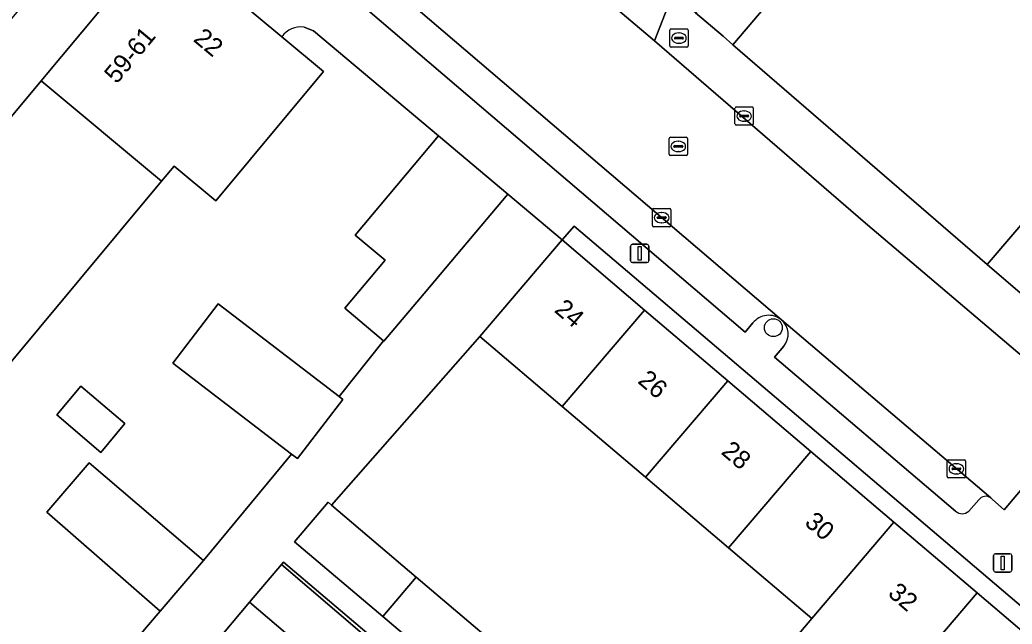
# Model space of a CAD drawing. Extents: x 162523 to 163266, y 381230 to 382050.
# Drawn here: x 162984.5 to 163038.7, y 381611.9 to 381644.9 of the extents above; entities that cross this region are included whole.
import ezdxf

# ---------------------------------------------------------------- set-up
doc = ezdxf.new("R2010")
doc.units = 0
for name, color, linetype in [('IMGEO_Boom', 7, 'Continuous'), ('IMGEO_Brandkraan', 7, 'Continuous'), ('IMGEO_Erf', 7, 'Continuous'), ('IMGEO_Kolk', 7, 'Continuous'), ('IMGEO_Lichtmast', 7, 'Continuous'), ('IMGEO_Muur', 7, 'Continuous'), ('IMGEO_Pand', 7, 'Continuous'), ('IMGEO_Pand_nummerreeks', 7, 'Continuous'), ('IMGEO_Parkeervlak_open', 7, 'Continuous'), ('IMGEO_Rijbaan_lokaal_open', 7, 'Continuous'), ('IMGEO_Rioolput', 7, 'Continuous'), ('IMGEO_Voetpad_open', 7, 'Continuous')]:
    doc.layers.add(name, color=color, linetype=linetype)

msp = doc.modelspace()

# ---------------------------------------------------------------- linework, layer by layer
at = {"layer": 'IMGEO_Boom'}
msp.add_circle((163025.628, 381628.108), 0.489, dxfattribs=at)
at = {"layer": 'IMGEO_Brandkraan'}
for p, q in [((163019.972, 381643.501), (163019.972, 381644.353)), ((163020.047, 381644.427), (163020.899, 381644.427)), ((163020.274, 381643.97), (163020.672, 381643.97)), ((163020.46, 381644.207), (163020.485, 381644.207)), ((163020.973, 381644.353), (163020.973, 381643.501)), ((163020.899, 381643.427), (163020.047, 381643.427)), ((163020.231, 381643.921), (163020.231, 381643.933)), ((163020.669, 381643.884), (163020.271, 381643.884)), ((163020.483, 381643.647), (163020.458, 381643.647)), ((163020.715, 381643.933), (163020.715, 381643.921))]:
    msp.add_line(p, q, dxfattribs=at)
for points in [[(163019.972, 381643.501), (163019.972, 381644.353)], [(163020.047, 381644.427), (163020.899, 381644.427)], [(163020.973, 381644.353), (163020.973, 381643.501)], [(163020.899, 381643.427), (163020.047, 381643.427)]]:
    msp.add_lwpolyline(points, dxfattribs=at)
for centre, radius, start, end in [((163020.049, 381644.351), 0.0765, 91.552, 178.448), ((163020.049, 381644.351), 0.0765, 91.552, 178.448), ((163020.271, 381643.93), 0.0403, 85.8775, 175.7526), ((163020.676, 381643.932), 0.0386, 1.7309, 96.639), ((163020.897, 381644.351), 0.0765, 1.552, 88.448), ((163020.897, 381644.351), 0.0765, 1.552, 88.448), ((163020.049, 381643.503), 0.0765, 181.552, 268.448), ((163020.049, 381643.503), 0.0765, 181.552, 268.448), ((163020.268, 381643.92), 0.0366, 178.938, 274.7102), ((163020.672, 381643.927), 0.043, 264.8664, 352.4533), ((163020.897, 381643.503), 0.0765, 271.552, 358.448), ((163020.897, 381643.503), 0.0765, 271.552, 358.448)]:
    msp.add_arc(centre, radius, start, end, dxfattribs=at)
for centre, major_axis, ratio, start_param, end_param in [((163020.459, 381643.927), (-0.387, 0.002), 0.722429, 4.712389, 7.853982), ((163020.484, 381643.927), (-0.39, 0.002), 0.717154, 1.570796, 4.712389)]:
    msp.add_ellipse(centre, major_axis=major_axis, ratio=ratio, start_param=start_param, end_param=end_param, dxfattribs=at)
at = {"layer": 'IMGEO_Erf'}
for points in [[(163052.984, 381649.884), (163038.896, 381661.976), (163039.043, 381662.152), (163036.865, 381663.973), (163032.907, 381659.241), (163029.084, 381654.669), (163026.979, 381652.153), (163027.1, 381652.052), (163028.379, 381653.56), (163030.41, 381651.829), (163029.157, 381650.331), (163027.372, 381648.229), (163023.415, 381643.568), (163037.297, 381631.564), (163041.391, 381636.346), (163039.229, 381638.189), (163042.925, 381642.504), (163045.087, 381640.661), (163045.268, 381640.873), (163049.144, 381645.4)], [(162990.207, 381622.865), (162988.9, 381621.297), (162986.503, 381623.352), (162987.81, 381624.92)]]:
    msp.add_lwpolyline(points, close=True, dxfattribs=at)
for points in [[(162992.84, 381626.178), (162995.319, 381629.408), (163001.912, 381624.349), (163004.342, 381627.383), (163002.22, 381629.169), (163004.423, 381631.788), (163002.787, 381633.164), (163007.344, 381638.581), (163000.523, 381644.317), (163000, 381644.529)], [(162998.792, 381643.994), (163001.064, 381642.099), (162997.07, 381637.309), (162995.177, 381635.039), (162992.905, 381636.933), (162992.217, 381636.108), (162978.832, 381620.055), (162971.989, 381611.847), (162983.414, 381602.297), (162985.204, 381604.439), (162980.992, 381607.96), (162983.166, 381610.561), (162987.378, 381607.04), (162992.138, 381612.621), (162985.957, 381618.029), (162988.275, 381620.732), (162994.51, 381615.388), (162999.317, 381621.207), (162992.84, 381626.178)], [(163025.811, 381609.964), (163027.724, 381612.212), (163023.184, 381616.074), (163018.644, 381619.935), (163014.104, 381623.797), (163009.603, 381627.625), (163001.502, 381618.411), (163006.131, 381614.483), (163010.681, 381610.623)], [(163003.429, 381611.437), (162998.887, 381615.303), (162998.764, 381615.162), (163003.308, 381611.294)], [(163001.568, 381609.238), (162997.018, 381613.111), (162989.08, 381603.646)]]:
    msp.add_lwpolyline(points, dxfattribs=at)
msp.add_arc((162999.815, 381643.316), 1.227, 81.3199, 146.4554, dxfattribs=at)
at = {"layer": 'IMGEO_Kolk'}
for p, q in [((163023.608, 381640.167), (163024.46, 381640.167)), ((163023.533, 381639.241), (163023.533, 381640.093)), ((163023.792, 381639.661), (163023.792, 381639.673)), ((163024.23, 381639.624), (163023.832, 381639.624)), ((163023.835, 381639.71), (163024.233, 381639.71)), ((163024.021, 381639.947), (163024.046, 381639.947)), ((163024.276, 381639.673), (163024.276, 381639.661)), ((163024.534, 381640.093), (163024.534, 381639.241)), ((163024.46, 381639.167), (163023.608, 381639.167)), ((163024.044, 381639.387), (163024.019, 381639.387)), ((163019.028, 381633.693), (163019.028, 381634.545)), ((163019.103, 381634.619), (163019.955, 381634.619)), ((163019.516, 381634.399), (163019.541, 381634.399)), ((163020.029, 381634.545), (163020.029, 381633.693)), ((163019.287, 381634.113), (163019.287, 381634.125)), ((163019.725, 381634.076), (163019.327, 381634.076)), ((163019.33, 381634.162), (163019.728, 381634.162)), ((163019.539, 381633.839), (163019.514, 381633.839)), ((163019.771, 381634.125), (163019.771, 381634.113)), ((163019.955, 381633.619), (163019.103, 381633.619)), ((163035.12, 381619.971), (163035.12, 381620.823)), ((163035.195, 381620.897), (163036.047, 381620.897)), ((163035.608, 381620.677), (163035.633, 381620.677)), ((163036.121, 381620.823), (163036.121, 381619.971)), ((163035.379, 381620.391), (163035.379, 381620.403)), ((163035.817, 381620.354), (163035.419, 381620.354)), ((163035.422, 381620.44), (163035.82, 381620.44)), ((163035.631, 381620.117), (163035.606, 381620.117)), ((163035.863, 381620.403), (163035.863, 381620.391)), ((163036.047, 381619.897), (163035.195, 381619.897))]:
    msp.add_line(p, q, dxfattribs=at)
for points in [[(163023.608, 381640.167), (163024.46, 381640.167)], [(163023.533, 381639.241), (163023.533, 381640.093)], [(163024.534, 381640.093), (163024.534, 381639.241)], [(163024.46, 381639.167), (163023.608, 381639.167)], [(163019.028, 381633.693), (163019.028, 381634.545)], [(163019.103, 381634.619), (163019.955, 381634.619)], [(163020.029, 381634.545), (163020.029, 381633.693)], [(163019.955, 381633.619), (163019.103, 381633.619)], [(163035.12, 381619.971), (163035.12, 381620.823)], [(163035.195, 381620.897), (163036.047, 381620.897)], [(163036.121, 381620.823), (163036.121, 381619.971)], [(163036.047, 381619.897), (163035.195, 381619.897)]]:
    msp.add_lwpolyline(points, dxfattribs=at)
for centre, radius, start, end in [((163023.61, 381640.091), 0.0765, 91.552, 178.448), ((163023.61, 381640.091), 0.0765, 91.552, 178.448), ((163024.458, 381640.091), 0.0765, 1.552, 88.448), ((163024.458, 381640.091), 0.0765, 1.552, 88.448), ((163023.832, 381639.67), 0.0403, 85.8775, 175.7526), ((163023.829, 381639.66), 0.0366, 178.938, 274.7102), ((163024.233, 381639.667), 0.043, 264.8664, 352.4533), ((163024.237, 381639.672), 0.0386, 1.7309, 96.639), ((163023.61, 381639.243), 0.0765, 181.552, 268.448), ((163023.61, 381639.243), 0.0765, 181.552, 268.448), ((163024.458, 381639.243), 0.0765, 271.552, 358.448), ((163024.458, 381639.243), 0.0765, 271.552, 358.448), ((163019.105, 381634.543), 0.0765, 91.552, 178.448), ((163019.105, 381634.543), 0.0765, 91.552, 178.448), ((163019.953, 381634.543), 0.0765, 1.552, 88.448), ((163019.953, 381634.543), 0.0765, 1.552, 88.448), ((163019.105, 381633.695), 0.0765, 181.552, 268.448), ((163019.105, 381633.695), 0.0765, 181.552, 268.448), ((163019.327, 381634.122), 0.0403, 85.8775, 175.7526), ((163019.324, 381634.112), 0.0366, 178.938, 274.7102), ((163019.728, 381634.119), 0.043, 264.8664, 352.4533), ((163019.732, 381634.124), 0.0386, 1.7309, 96.639), ((163019.953, 381633.695), 0.0765, 271.552, 358.448), ((163019.953, 381633.695), 0.0765, 271.552, 358.448), ((163035.197, 381620.821), 0.0765, 91.552, 178.448), ((163035.197, 381620.821), 0.0765, 91.552, 178.448), ((163036.045, 381620.821), 0.0765, 1.552, 88.448), ((163036.045, 381620.821), 0.0765, 1.552, 88.448), ((163035.419, 381620.4), 0.0403, 85.8775, 175.7526), ((163035.416, 381620.39), 0.0366, 178.938, 274.7102), ((163035.82, 381620.397), 0.043, 264.8664, 352.4533), ((163035.824, 381620.402), 0.0386, 1.7309, 96.639), ((163035.197, 381619.973), 0.0765, 181.552, 268.448), ((163035.197, 381619.973), 0.0765, 181.552, 268.448), ((163036.045, 381619.973), 0.0765, 271.552, 358.448), ((163036.045, 381619.973), 0.0765, 271.552, 358.448)]:
    msp.add_arc(centre, radius, start, end, dxfattribs=at)
for centre, major_axis, ratio, start_param, end_param in [((163024.02, 381639.667), (-0.387, 0.002), 0.722429, 4.712389, 7.853982), ((163024.045, 381639.667), (-0.39, 0.002), 0.717154, 1.570796, 4.712389), ((163019.515, 381634.119), (-0.387, 0.002), 0.722429, 4.712389, 7.853982), ((163019.54, 381634.119), (-0.39, 0.002), 0.717154, 1.570796, 4.712389), ((163035.607, 381620.397), (-0.387, 0.002), 0.722429, 4.712389, 7.853982), ((163035.632, 381620.397), (-0.39, 0.002), 0.717154, 1.570796, 4.712389)]:
    msp.add_ellipse(centre, major_axis=major_axis, ratio=ratio, start_param=start_param, end_param=end_param, dxfattribs=at)
at = {"layer": 'IMGEO_Lichtmast'}
for p, q in [((163017.933, 381632.665), (163018.723, 381632.665)), ((163018.723, 381632.665), (163017.933, 381632.665)), ((163017.833, 381631.765), (163017.833, 381632.565)), ((163017.833, 381632.565), (163017.833, 381631.765)), ((163018.823, 381632.565), (163018.823, 381631.765)), ((163018.823, 381631.765), (163018.823, 381632.565)), ((163018.723, 381631.665), (163017.933, 381631.665)), ((163017.933, 381631.665), (163018.723, 381631.665)), ((163037.655, 381614.857), (163037.655, 381615.657)), ((163037.655, 381615.657), (163037.655, 381614.857)), ((163037.755, 381615.757), (163038.545, 381615.757)), ((163038.545, 381615.757), (163037.755, 381615.757)), ((163038.645, 381615.657), (163038.645, 381614.857)), ((163038.645, 381614.857), (163038.645, 381615.657)), ((163038.545, 381614.757), (163037.755, 381614.757)), ((163037.755, 381614.757), (163038.545, 381614.757))]:
    msp.add_line(p, q, dxfattribs=at)
for points in [[(163018.253, 381632.54), (163018.403, 381632.54), (163018.403, 381631.79), (163018.253, 381631.79), (163018.253, 381632.54)], [(163038.075, 381615.632), (163038.225, 381615.632), (163038.225, 381614.882), (163038.075, 381614.882), (163038.075, 381615.632)]]:
    msp.add_lwpolyline(points, dxfattribs=at)
for centre, start, end in [((163017.933, 381632.565), 90, 180), ((163017.933, 381632.565), 90, 180), ((163018.723, 381632.565), 0, 90), ((163018.723, 381632.565), 360, 90), ((163017.933, 381631.765), 180, 270), ((163017.933, 381631.765), 180, 270), ((163018.723, 381631.765), 270, 0), ((163018.723, 381631.765), 270, 0), ((163037.755, 381615.657), 90, 180), ((163037.755, 381615.657), 90, 180), ((163038.545, 381615.657), 0, 90), ((163038.545, 381615.657), 360, 90), ((163037.755, 381614.857), 180, 270), ((163037.755, 381614.857), 180, 270), ((163038.545, 381614.857), 270, 0), ((163038.545, 381614.857), 270, 0)]:
    msp.add_arc(centre, 0.1, start, end, dxfattribs=at)
at = {"layer": 'IMGEO_Muur'}
msp.add_lwpolyline([(163000, 381644.529), (163000.523, 381644.317), (163007.344, 381638.581)], dxfattribs=at)
msp.add_arc((162999.815, 381643.316), 1.227, 81.3199, 146.4554, dxfattribs=at)
at = {"layer": 'IMGEO_Pand'}
for points in [[(163027.372, 381648.229), (163026.866, 381648.728), (163025.365, 381650.007), (163021.376, 381645.308), (163022.88, 381644.031), (163023.415, 381643.568)], [(162985.642, 381641.585), (162992.217, 381636.108), (162992.905, 381636.933), (162995.177, 381635.039), (162997.07, 381637.309), (163001.064, 381642.099), (162998.792, 381643.994), (162992.216, 381649.474)], [(162985.642, 381641.585), (162972.261, 381625.529), (162978.832, 381620.055), (162992.217, 381636.108)], [(163011.124, 381635.401), (163007.344, 381638.581), (163002.787, 381633.164), (163004.423, 381631.788), (163002.22, 381629.169), (163004.342, 381627.383), (163004.364, 381627.365), (163006.567, 381629.984)], [(163041.391, 381636.346), (163037.297, 381631.564), (163042.545, 381627.069), (163046.65, 381631.863)], [(163014.104, 381623.797), (163018.595, 381629.073), (163014.093, 381632.903), (163010.854, 381629.095), (163009.603, 381627.625)], [(162995.319, 381629.408), (162992.84, 381626.178), (162999.317, 381621.207), (162999.637, 381620.962), (163002.116, 381624.193), (163001.912, 381624.349)], [(163023.135, 381625.211), (163018.595, 381629.073), (163014.104, 381623.797), (163018.644, 381619.935)], [(163018.644, 381619.935), (163023.184, 381616.074), (163027.674, 381621.349), (163023.135, 381625.211)], [(162986.503, 381623.352), (162988.9, 381621.297), (162990.207, 381622.865), (162987.81, 381624.92)], [(163032.213, 381617.487), (163027.674, 381621.349), (163023.184, 381616.074), (163027.724, 381612.212)], [(162988.275, 381620.732), (162985.957, 381618.029), (162992.138, 381612.621), (162994.51, 381615.388)], [(163001.502, 381618.411), (163001.318, 381618.567), (162999.485, 381616.407), (163004.295, 381612.326), (163006.131, 381614.483)], [(163032.213, 381617.487), (163027.724, 381612.212), (163025.811, 381609.964), (163030.35, 381606.102), (163032.264, 381608.351), (163036.752, 381613.625)], [(162998.764, 381615.162), (162997.018, 381613.111), (163001.568, 381609.238), (163003.308, 381611.294)], [(163006.131, 381614.483), (163004.295, 381612.326), (163008.845, 381608.466), (163010.681, 381610.623)], [(163036.752, 381613.625), (163032.264, 381608.351), (163036.804, 381604.49), (163041.292, 381609.763)]]:
    msp.add_lwpolyline(points, close=True, dxfattribs=at)
at = {"layer": 'IMGEO_Parkeervlak_open'}
for points in [[(163026.073, 381628.53), (163002.267, 381648.879), (163000, 381650.805), (162996.446, 381653.717), (162993.71, 381656.023)], [(162994.852, 381652.638), (163000, 381648.444), (163024.092, 381627.869), (163024.51, 381628.365)], [(163037.494, 381618.804), (163026.073, 381628.53)], [(163026.205, 381627.096), (163025.694, 381626.501), (163035.579, 381618.086)], [(163036.296, 381618.09), (163036.851, 381618.708)]]:
    msp.add_lwpolyline(points, dxfattribs=at)
for centre, radius, start, end in [((163025.371, 381627.695), 1.091, 49.925, 142.1274), ((163025.391, 381627.744), 1.041, 321.485, 49.0335), ((163037.22, 381618.441), 0.455, 52.9205, 144.0625), ((163035.935, 381618.473), 0.526, 227.3801, 313.2592)]:
    msp.add_arc(centre, radius, start, end, dxfattribs=at)
at = {"layer": 'IMGEO_Rijbaan_lokaal_open'}
msp.add_lwpolyline([(162997.235, 381660.07), (162993.71, 381656.023), (162996.446, 381653.717), (163000, 381650.805), (163002.267, 381648.879), (163026.073, 381628.53), (163037.494, 381618.804), (163037.585, 381618.725), (163038.229, 381618.164), (163040.501, 381620.847), (163042.772, 381623.53), (163042.103, 381624.099), (163030.666, 381633.822), (163019.14, 381643.77), (163015.837, 381646.586), (163000.436, 381659.433)], dxfattribs=at)
at = {"layer": 'IMGEO_Rioolput'}
for p, q in [((163019.937, 381637.584), (163019.937, 381638.436)), ((163020.012, 381638.51), (163020.864, 381638.51)), ((163020.196, 381638.004), (163020.196, 381638.016)), ((163020.239, 381638.053), (163020.637, 381638.053)), ((163020.425, 381638.29), (163020.45, 381638.29)), ((163020.68, 381638.016), (163020.68, 381638.004)), ((163020.938, 381638.436), (163020.938, 381637.584)), ((163020.864, 381637.51), (163020.012, 381637.51)), ((163020.634, 381637.967), (163020.236, 381637.967)), ((163020.448, 381637.73), (163020.423, 381637.73))]:
    msp.add_line(p, q, dxfattribs=at)
for points in [[(163019.937, 381637.584), (163019.937, 381638.436)], [(163020.012, 381638.51), (163020.864, 381638.51)], [(163020.938, 381638.436), (163020.938, 381637.584)], [(163020.864, 381637.51), (163020.012, 381637.51)]]:
    msp.add_lwpolyline(points, dxfattribs=at)
for centre, radius, start, end in [((163020.014, 381638.434), 0.0765, 91.552, 178.448), ((163020.014, 381638.434), 0.0765, 91.552, 178.448), ((163020.236, 381638.013), 0.0403, 85.8775, 175.7526), ((163020.233, 381638.003), 0.0366, 178.938, 274.7102), ((163020.637, 381638.01), 0.043, 264.8664, 352.4533), ((163020.641, 381638.015), 0.0386, 1.7309, 96.639), ((163020.862, 381638.434), 0.0765, 1.552, 88.448), ((163020.862, 381638.434), 0.0765, 1.552, 88.448), ((163020.014, 381637.586), 0.0765, 181.552, 268.448), ((163020.014, 381637.586), 0.0765, 181.552, 268.448), ((163020.862, 381637.586), 0.0765, 271.552, 358.448), ((163020.862, 381637.586), 0.0765, 271.552, 358.448)]:
    msp.add_arc(centre, radius, start, end, dxfattribs=at)
for centre, major_axis, ratio, start_param, end_param in [((163020.424, 381638.01), (-0.387, 0.002), 0.722429, 4.712389, 7.853982), ((163020.449, 381638.01), (-0.39, 0.002), 0.717154, 1.570796, 4.712389)]:
    msp.add_ellipse(centre, major_axis=major_axis, ratio=ratio, start_param=start_param, end_param=end_param, dxfattribs=at)
at = {"layer": 'IMGEO_Voetpad_open'}
for points in [[(162988.686, 381658.949), (162985.305, 381654.899), (162987.081, 381653.4), (162989.392, 381651.45), (162992.216, 381649.474), (162998.792, 381643.994)], [(163024.51, 381628.365), (163024.092, 381627.869), (163000, 381648.444), (162994.852, 381652.638)], [(163090.743, 381585.944), (163054.249, 381616.985), (163051.387, 381619.557), (163049.198, 381621.524), (163046.532, 381623.783), (163043.741, 381626.048), (163042.545, 381627.069), (163037.297, 381631.564), (163023.415, 381643.568), (163022.88, 381644.031), (163021.376, 381645.308), (163020.138, 381646.369), (163019.14, 381643.77), (163030.666, 381633.822), (163042.103, 381624.099), (163042.772, 381623.53), (163040.501, 381620.847), (163042.59, 381619.106), (163044.874, 381621.804), (163047.512, 381619.562), (163045.228, 381616.857), (163047.311, 381615.079), (163049.581, 381617.775), (163073.333, 381597.517)], [(163000, 381644.529), (163000.523, 381644.317), (163007.344, 381638.581), (163011.124, 381635.401), (163014.093, 381632.903), (163014.757, 381633.658), (163035.384, 381616.107), (163069.377, 381587.184), (163068.742, 381586.409), (163066.867, 381584.206), (163067.892, 381583.334), (163072.717, 381579.194), (163076.458, 381575.825), (163079.637, 381572.9), (163085.215, 381567.768), (163087.943, 381565.297)], [(163008.845, 381608.466), (163004.295, 381612.326), (162999.485, 381616.407), (163001.318, 381618.567), (163001.502, 381618.411), (163009.603, 381627.625), (163010.854, 381629.095), (163014.093, 381632.903), (163011.124, 381635.401), (163006.567, 381629.984), (163004.364, 381627.365), (163004.342, 381627.383), (163001.912, 381624.349), (163002.116, 381624.193), (162999.637, 381620.962), (162999.317, 381621.207), (162994.51, 381615.388), (162992.138, 381612.621), (162987.378, 381607.04)], [(163035.579, 381618.086), (163025.694, 381626.501), (163026.205, 381627.096)], [(163045.94, 381611.622), (163045.04, 381612.383), (163047.311, 381615.079), (163045.228, 381616.857), (163042.943, 381614.151), (163040.306, 381616.407), (163042.59, 381619.106), (163040.501, 381620.847), (163038.229, 381618.164), (163037.585, 381618.725), (163037.494, 381618.804)], [(163036.851, 381618.708), (163036.296, 381618.09)], [(162989.08, 381603.646), (162997.018, 381613.111), (162998.764, 381615.162), (162998.887, 381615.303), (163003.429, 381611.437)]]:
    msp.add_lwpolyline(points, dxfattribs=at)
for points in [[(162985.642, 381641.585), (162992.216, 381649.474), (162989.392, 381651.45), (162987.652, 381649.36), (162976.719, 381636.232), (162972.599, 381639.672), (162971.618, 381638.5), (162975.747, 381635.074), (162963.08, 381619.865), (162958.942, 381623.327), (162957.284, 381621.356), (162961.41, 381617.917), (162958.958, 381614.986), (162961.61, 381612.777), (162964.065, 381615.701), (162965.42, 381617.32), (162972.261, 381625.529)], [(163019.14, 381643.77), (163020.138, 381646.369), (163017.971, 381648.209), (163015.837, 381646.586)], [(163035.384, 381616.107), (163014.757, 381633.658), (163014.093, 381632.903), (163018.595, 381629.073), (163023.135, 381625.211), (163027.674, 381621.349), (163032.213, 381617.487), (163036.752, 381613.625), (163041.292, 381609.763), (163045.832, 381605.9), (163050.371, 381602.039), (163054.91, 381598.177), (163059.45, 381594.315), (163063.989, 381590.453), (163068.742, 381586.409), (163069.377, 381587.184)]]:
    msp.add_lwpolyline(points, close=True, dxfattribs=at)
for centre, radius, start, end in [((162999.815, 381643.316), 1.227, 81.3199, 146.4554), ((163025.371, 381627.695), 1.091, 49.925, 142.1274), ((163025.391, 381627.744), 1.041, 321.485, 49.0335), ((163037.22, 381618.441), 0.455, 52.9205, 144.0625), ((163035.935, 381618.473), 0.526, 227.3801, 313.2592)]:
    msp.add_arc(centre, radius, start, end, dxfattribs=at)

# ---------------------------------------------------------------- texts
at = {"layer": 'IMGEO_Pand_nummerreeks'}
for s, rotation, p in [('59-61', 50.3558, (162989.774, 381641.381)), ('22', 320.1893, (162993.903, 381643.798)), ('24', 319.6097, (163013.615, 381629.003)), ('26', 319.6122, (163018.169, 381625.128)), ('28', 319.6097, (163022.725, 381621.252)), ('30', 319.6097, (163027.279, 381617.377)), ('32', 319.6097, (163031.829, 381613.507))]:
    msp.add_text(s, height=1, rotation=rotation, dxfattribs=at).set_placement(p)

doc.saveas('drawing.dxf')
